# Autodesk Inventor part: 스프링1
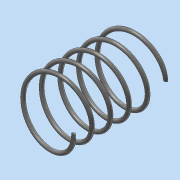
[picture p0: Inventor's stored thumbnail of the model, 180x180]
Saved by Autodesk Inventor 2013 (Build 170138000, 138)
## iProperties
Created: 2015-11
Part Number: 스프링1
Material: 강철, 탄소
Document SubType Name: Modeling
Designer: dgall
Density: 7.87 g/cm^3
Mass: 1.54771 g
Surface Area: 7.88792 cm^2
Volume: 0.19666 cm^3
Author: dgall
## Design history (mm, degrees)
sketch "스케치1"
  geometry: L1 (0, 0)-(8, 0); L2 (0, 0)-(0, 16.67); L3 (0, 16.67)-(8, 16.67); C1 r 0.5 at (8, 0)
  constraints: 6 end point, 2 perpendicular, 1 centre point, 1 coincident, 1 horizontal, 1 vertical alignment
  dimensions: "d0" = 16 diameter of L1.end L2; "d2" = 16.66987 distance of L1.start L2.end (derived); "d3" = 1 diameter of C1
feature "코일1" sketch "스케치1" pitch "d4" = 10; turns "d6" = 5; dims "d5" = 16.66987 (= d2), "d7" = 0, angle "d8" = 90 deg, angle "d9" = 90 deg, "d10" = 0, "d11" = 0
node "작업 평면1"
feature "분할1"
feature "분할2"
node "솔리드1"
other parameters: "d12" = 25
